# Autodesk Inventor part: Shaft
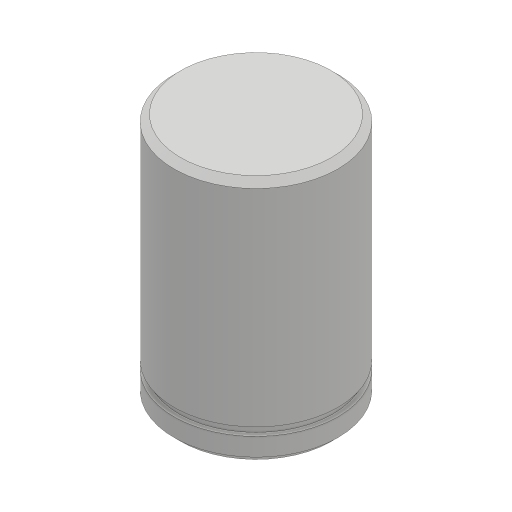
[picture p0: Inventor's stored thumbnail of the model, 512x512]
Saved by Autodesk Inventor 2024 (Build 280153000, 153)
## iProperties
Created: 2016-08
Part Number: Shaft
Material: Generic
Document SubType Name: Modeling
Designer: Sandeep
Density: 1 g/cm^3
Appearance: Default
Author: Sandeep
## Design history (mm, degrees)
sketch "Sketch1"
  geometry: C1 r 25 at (0, 0); 1 further point
  constraints: 1 centre point, 1 coincident
  dimensions: "d0" = 50 diameter of C1
extrude "Extrusion1" new body sketch "Sketch1" stored distance "d1" = 75; taper "d2" = 0 deg
sketch "Sketch2"
  geometry: L1 (-25, -37.5)-(-25, 37.5) reference; L2 (-25, -30)-(-23.5, -30); L3 (-23.5, -30)-(-23.5, -27.5); L4 (-23.5, -27.5)-(-25, -27.5); L5 (-25, -27.5)-(-25, -30); L6 (0, 0)-(0, -83)
  constraints: 10 end point, 2 parallel, 1 horizontal, 1 perpendicular, 1 point on line, 1 vertical
  dimensions: "d3" = 2.5 distance between parallel lines of L2 L4; "d4" = 47 diameter of L3 L6; "d5" = 7.5 distance from line of L2 L1.start
revolve "Revolution1" sketch "Sketch2" stored, may be unused: angle "d6" = 90 deg
chamfer "Chamfer1" distance "d7" = 2; stored, may be unused: second distance "d8" = 2, angle "d9" = 45 deg
body "Solid1"
other parameters: "d10" = 0
